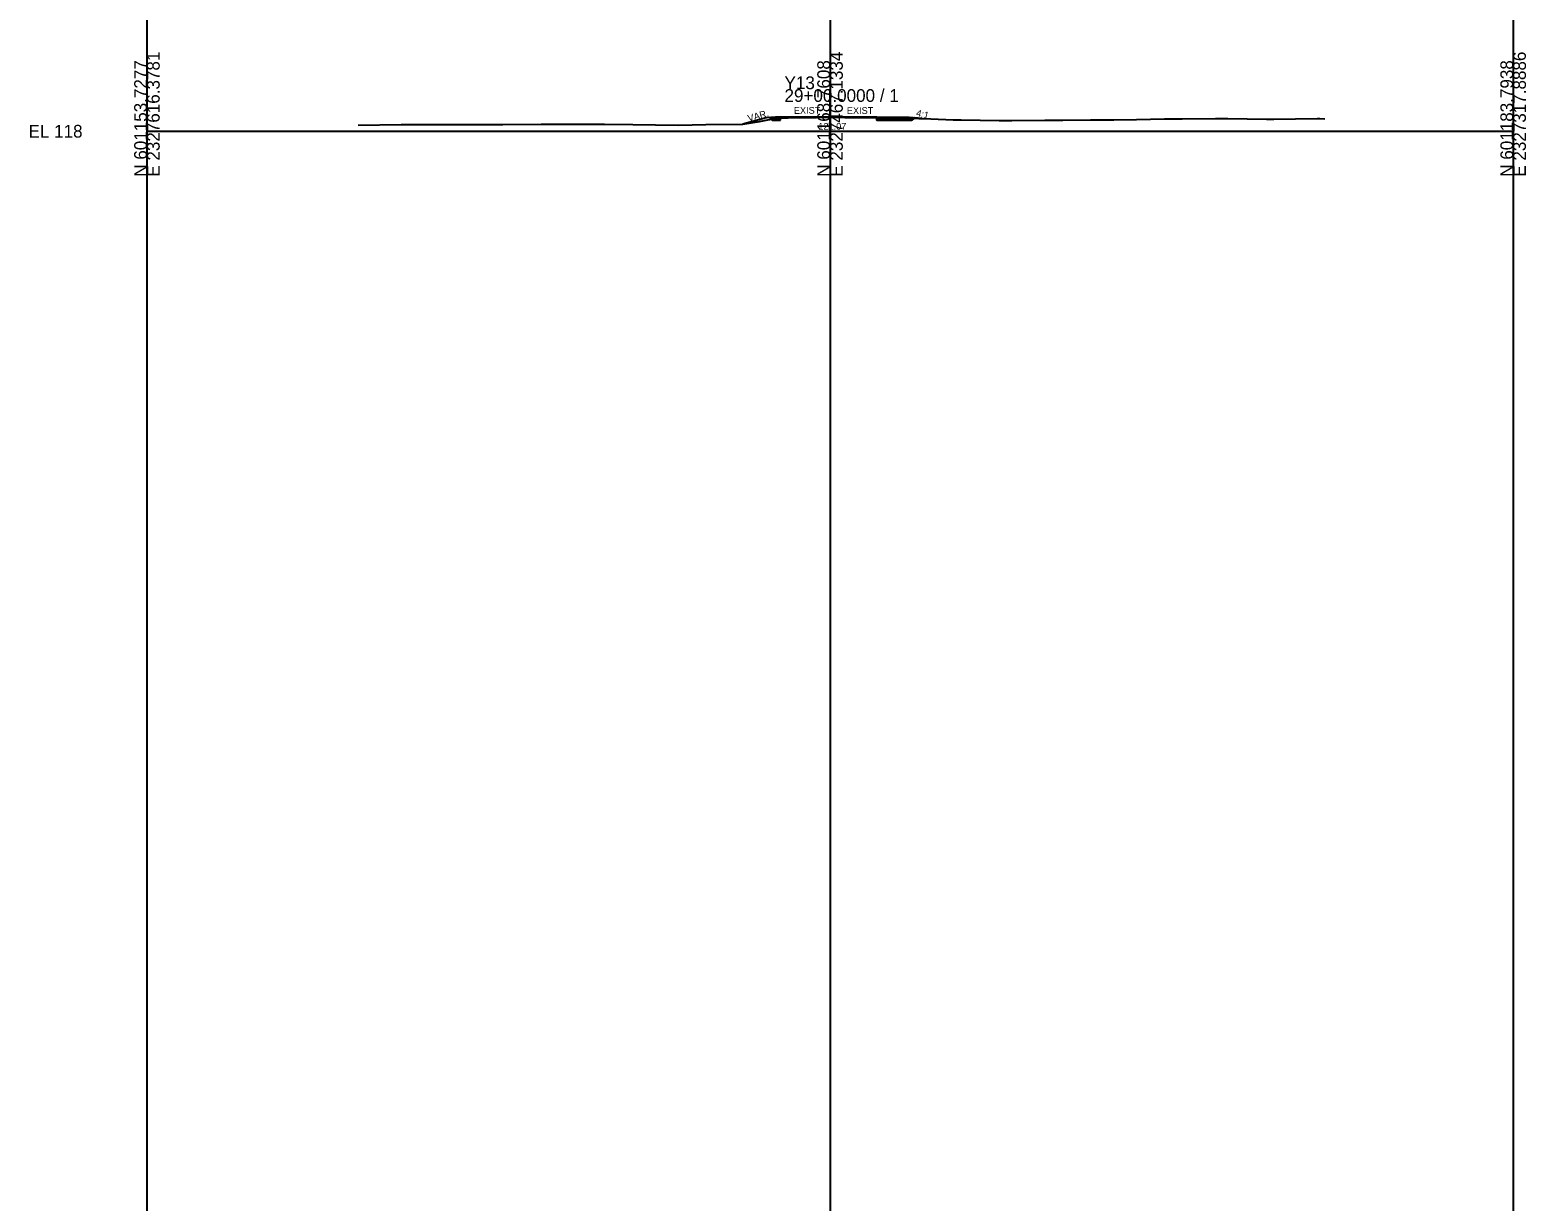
# Model space of a CAD drawing. Extents: x -26 to 1603, y -711 to 1241.
# Drawn here: x 1274.3 to 1602.8, y 265 to 522.3 of the extents above; entities that cross this region are included whole.
import ezdxf

# ---------------------------------------------------------------- set-up
doc = ezdxf.new("R2010")
doc.units = 0
for name, color, linetype in [('Exist CMT Pavement', 7, 'Continuous'), ('Exist Cross Section Cell', 7, 'Continuous'), ('Exist XS Center Line Elevation Label', 7, 'Continuous'), ('Exist XS Ground Line', 7, 'Continuous'), ('Prop CMT Pvmt Course 1', 7, 'Continuous'), ('Prop CMT Pvmt Course 1 Wedge', 7, 'Continuous'), ('Prop CMT Pvmt Course 2', 7, 'Continuous'), ('Prop CMT Pvmt Course 3', 7, 'Continuous'), ('Prop CMT Pvmt Surface', 7, 'Continuous'), ('Prop CMT Pvmt Surface Shoulder', 7, 'Continuous'), ('Prop CMT Pvmt Wedge Surface 1', 7, 'Continuous'), ('Prop CMT Pvmt Wedge Surface 2', 7, 'Continuous'), ('Prop CMT Pvmt Wedge Surface 3', 7, 'Continuous'), ('Prop CMT Shld Paved Course 1', 7, 'Continuous'), ('Prop CMT Shld Paved Course 2', 7, 'Continuous'), ('Prop CMT Shld Paved Course 3', 7, 'Continuous'), ('Prop CMT Slope Grass', 7, 'Continuous'), ('Prop CMT Subgrade Earthwork', 7, 'Continuous'), ('Prop XS Earthwork Shape', 7, 'Continuous'), ('Prop XS SE Text', 7, 'Continuous'), ('Prop XS Side Slope Text', 7, 'Continuous'), ('Scratch_Level_0', 7, 'Continuous'), ('Scratch_Level_1', 7, 'Continuous'), ('Scratch_Level_9', 7, 'Continuous')]:
    doc.layers.add(name, color=color, linetype=linetype)

msp = doc.modelspace()

# ---------------------------------------------------------------- linework, layer by layer
at = {"layer": 'Exist CMT Pavement'}
msp.add_lwpolyline([(1439.15, 502.9), (1439.15, 502.9), (1440.8, 502.93), (1443.52, 502.99), (1444.59, 503.01), (1446.49, 503.04), (1447.03, 503.05), (1448.97, 503.07), (1449.8, 503.06), (1450.32, 503.07), (1450.87, 503.06), (1451.7, 503.06), (1453.28, 503.05), (1454.43, 503.04), (1455.98, 503.03), (1457.16, 503.02), (1457.88, 503.02), (1459.54, 503), (1459.92, 502.99), (1460.28, 502.99), (1460.28, 502.99)], dxfattribs=at)
at = {"layer": 'Exist Cross Section Cell'}
for p, q in [((1450, 500), (1450, 509.24)), ((1300, 500), (1450, 500)), ((1450, 500), (1600, 500))]:
    msp.add_line(p, q, dxfattribs=at)
at = {"layer": 'Exist XS Ground Line'}
msp.add_lwpolyline([(1346.4, 501.34), (1355.8, 501.44), (1356.45, 501.44), (1362.22, 501.44), (1366.5, 501.44), (1366.98, 501.44), (1376.55, 501.51), (1378.16, 501.51), (1386.6, 501.53), (1389.33, 501.53), (1396.65, 501.56), (1400.51, 501.54), (1406.71, 501.48), (1411.69, 501.37), (1416.76, 501.31), (1422.71, 501.45), (1430.86, 501.54), (1434.51, 502.17), (1438.28, 502.89), (1438.76, 502.9), (1439.15, 502.9), (1440.8, 502.93), (1443.52, 502.99), (1444.59, 503.01), (1446.49, 503.04), (1447.03, 503.05), (1448.97, 503.07), (1449.8, 503.06), (1450.32, 503.07), (1450.87, 503.06), (1451.7, 503.06), (1453.28, 503.05), (1454.43, 503.04), (1455.98, 503.03), (1457.16, 503.02), (1457.88, 503.02), (1459.54, 503), (1459.92, 502.99), (1460.28, 502.99), (1461.14, 502.98), (1461.61, 502.99), (1472.15, 502.71), (1477.07, 502.52), (1478.76, 502.51), (1487.12, 502.33), (1489.93, 502.37), (1497.17, 502.41), (1501.11, 502.45), (1507.23, 502.48), (1512.29, 502.53), (1517.28, 502.61), (1523.47, 502.7), (1527.33, 502.71), (1534.64, 502.79), (1537.38, 502.81), (1545.82, 502.66), (1547.43, 502.66), (1557, 502.79), (1557.54, 502.78), (1558.64, 502.71)], dxfattribs=at)
at = {"layer": 'Prop CMT Pvmt Course 1'}
for points in [[(1450, 503.19), (1439.15, 503.09)], [(1439.15, 503.09), (1439.15, 502.84)], [(1450, 503.07), (1439.15, 502.96)], [(1439.15, 502.84), (1439.15, 502.96)], [(1450, 503.19), (1460.28, 503.13)], [(1460.28, 503), (1450, 503.07)], [(1460.28, 502.88), (1460.28, 503.13)], [(1460.28, 502.91), (1460.28, 502.88)]]:
    msp.add_lwpolyline(points, dxfattribs=at)
at = {"layer": 'Prop CMT Pvmt Course 1 Wedge'}
msp.add_lwpolyline([(1450, 503.07), (1460.28, 503)], dxfattribs=at)
at = {"layer": 'Prop CMT Pvmt Course 2'}
for points in [[(1439.15, 502.84), (1439.15, 502.84)], [(1460.28, 503), (1460.28, 503)], [(1460.28, 502.88), (1460.28, 502.88)]]:
    msp.add_lwpolyline(points, dxfattribs=at)
at = {"layer": 'Prop CMT Pvmt Course 3'}
for points in [[(1439.15, 502.42), (1439.15, 502.84)], [(1460.28, 502.88), (1460.28, 502.46)]]:
    msp.add_lwpolyline(points, dxfattribs=at)
at = {"layer": 'Prop CMT Pvmt Surface'}
for points in [[(1450, 503.19), (1439.15, 503.09)], [(1450, 503.19), (1460.28, 503.13)]]:
    msp.add_lwpolyline(points, dxfattribs=at)
at = {"layer": 'Prop CMT Pvmt Surface Shoulder'}
for points in [[(1439.15, 503.09), (1438, 503.08)], [(1460.28, 503.13), (1467.31, 503.08)]]:
    msp.add_lwpolyline(points, dxfattribs=at)
at = {"layer": 'Prop CMT Pvmt Wedge Surface 1'}
for points in [[(1439.15, 502.96), (1439.15, 502.84)], [(1450, 503.07), (1460.28, 503)], [(1460.28, 503.13), (1460.28, 503)], [(1460.28, 502.88), (1460.28, 502.91)]]:
    msp.add_lwpolyline(points, dxfattribs=at)
at = {"layer": 'Prop CMT Pvmt Wedge Surface 2'}
msp.add_lwpolyline([(1460.28, 502.88), (1460.28, 502.91)], dxfattribs=at)
at = {"layer": 'Prop CMT Pvmt Wedge Surface 3'}
msp.add_lwpolyline([(1460.28, 502.88), (1460.28, 502.91)], dxfattribs=at)
at = {"layer": 'Prop CMT Shld Paved Course 1'}
for points in [[(1439.15, 503.09), (1438, 503.08), (1437.72, 502.82)], [(1437.72, 502.82), (1439.15, 502.84)], [(1460.28, 503.13), (1467.31, 503.08), (1467.56, 502.83)], [(1460.28, 502.88), (1460.28, 502.91)], [(1467.53, 502.83), (1460.28, 502.88)]]:
    msp.add_lwpolyline(points, dxfattribs=at)
at = {"layer": 'Prop CMT Shld Paved Course 2'}
for points in [[(1439.15, 502.84), (1437.72, 502.82)], [(1437.72, 502.82), (1439.15, 502.84)], [(1437.74, 502.81), (1437.74, 502.81)], [(1460.28, 502.88), (1467.53, 502.83)], [(1467.53, 502.83), (1460.28, 502.88)], [(1460.28, 502.88), (1460.28, 502.88)]]:
    msp.add_lwpolyline(points, dxfattribs=at)
at = {"layer": 'Prop CMT Shld Paved Course 3'}
for points in [[(1437.74, 502.81), (1437.32, 502.4)], [(1439.15, 502.84), (1437.72, 502.82)], [(1437.74, 502.81), (1437.74, 502.81)], [(1460.28, 502.88), (1467.56, 502.83)], [(1460.28, 502.46), (1460.28, 502.88)], [(1467.56, 502.83), (1467.98, 502.41)], [(1437.32, 502.4), (1439.15, 502.42)], [(1467.27, 502.41), (1460.28, 502.46)]]:
    msp.add_lwpolyline(points, dxfattribs=at)
at = {"layer": 'Prop CMT Slope Grass'}
for p, q in [((1436, 502.92), (1430.86, 501.54)), ((1438, 503.08), (1436, 502.92)), ((1467.31, 503.08), (1469.31, 502.96)), ((1469.31, 502.96), (1470.12, 502.76))]:
    msp.add_line(p, q, dxfattribs=at)
at = {"layer": 'Prop CMT Subgrade Earthwork'}
for p, q in [((1439.15, 502.42), (1439.15, 502.9)), ((1460.28, 502.46), (1460.28, 502.99))]:
    msp.add_line(p, q, dxfattribs=at)
for points in [[(1437.32, 502.4), (1436.75, 502.98)], [(1467.98, 502.41), (1468.58, 503.01)], [(1439.15, 502.42), (1437.32, 502.4)], [(1460.28, 502.46), (1467.98, 502.41)]]:
    msp.add_lwpolyline(points, dxfattribs=at)
at = {"layer": 'Prop XS Earthwork Shape'}
for points in [[(1436.75, 502.98), (1436, 502.92), (1430.86, 501.54), (1434.51, 502.17), (1437.07, 502.66)], [(1439.15, 502.42), (1439.15, 502.9), (1438.76, 502.9), (1438.28, 502.89), (1437.07, 502.66), (1437.32, 502.4)], [(1461.14, 502.98), (1461.61, 502.99), (1468.38, 502.81), (1467.98, 502.41), (1460.28, 502.46), (1460.28, 502.99)], [(1469.31, 502.96), (1470.12, 502.76), (1468.38, 502.81), (1468.58, 503.01)]]:
    msp.add_lwpolyline(points, close=True, dxfattribs=at)
at = {"layer": 'Scratch_Level_1'}
msp.add_line((1450, 503.19), (1460.28, 503.13), dxfattribs=at)
at = {"layer": 'Scratch_Level_9'}
for p, q in [((1300, 1241.32), (1300, -141.18)), ((1450, 1241.32), (1450, -141.18)), ((1600, 1241.32), (1600, -141.18))]:
    msp.add_line(p, q, dxfattribs=at)

# ---------------------------------------------------------------- texts
at = {"layer": 'Exist Cross Section Cell'}
for s, p in [('E 2327616.3781', (1302.8, 490)), ('E 2327467.1334', (1452.8, 490)), ('E 2327317.8886', (1602.8, 490)), ('N 601153.7277', (1300, 490)), ('N 601168.7608', (1450, 490)), ('N 601183.7938', (1600, 490))]:
    msp.add_text(s, height=2.8, rotation=90, dxfattribs=at).set_placement(p)
for s, p in [('Y13', (1440, 509.24)), ('29+00.0000 / 1', (1440, 506.44)), ('EL 118', (1274, 498.6))]:
    msp.add_text(s, height=2.8, dxfattribs=at).set_placement(p)
at = {"layer": 'Exist XS Center Line Elevation Label'}
msp.add_text('121.07', height=1.5, dxfattribs=at).set_placement((1447.44, 500.32))
at = {"layer": 'Prop XS SE Text'}
for rotation, p in [(0.544, (1442.07, 503.8)), (0.3522, (1453.7, 503.76))]:
    msp.add_text('EXIST', height=1.5, rotation=rotation, dxfattribs=at).set_placement(p)
at = {"layer": 'Prop XS Side Slope Text'}
for s, rotation, p in [('VAR.', 15.0278, (1432.14, 502.07)), ('4:1', 345.9638, (1468.8, 503.36))]:
    msp.add_text(s, height=1.5, rotation=rotation, dxfattribs=at).set_placement(p)
at = {"layer": 'Scratch_Level_0'}
for s, p in [('LT_Sub_Trench_Out_DLT', (1436.56, 502.96)), ('LT_PS3_Shelf_Out', (1437.6, 502.8)), ('LT_PS3_OEOP', (1437.64, 502.8)), ('LT_PS2_OEOP', (1437.64, 502.8)), ('LT_PS1_OEOP', (1437.88, 503.04)), ('LT_PV2_OEEOP', (1439.05, 502.83)), ('LT_PV3_OEEOP', (1439.05, 502.83)), ('LT_PV1_OEEOP', (1439.05, 502.95)), ('RT_PS1_OEOP', (1467.24, 503.1)), ('RT_Sub_Trench_Out_DLT', (1468.38, 503)), ('LT_Sub_Trench_Out', (1437.18, 502.4)), ('LT_Sub_OEEOP', (1439.05, 502.41)), ('RT_Sub_Trench_Out', (1467.82, 502.4))]:
    msp.add_text(s, height=0.02, dxfattribs=at).set_placement(p)

doc.saveas('drawing.dxf')
